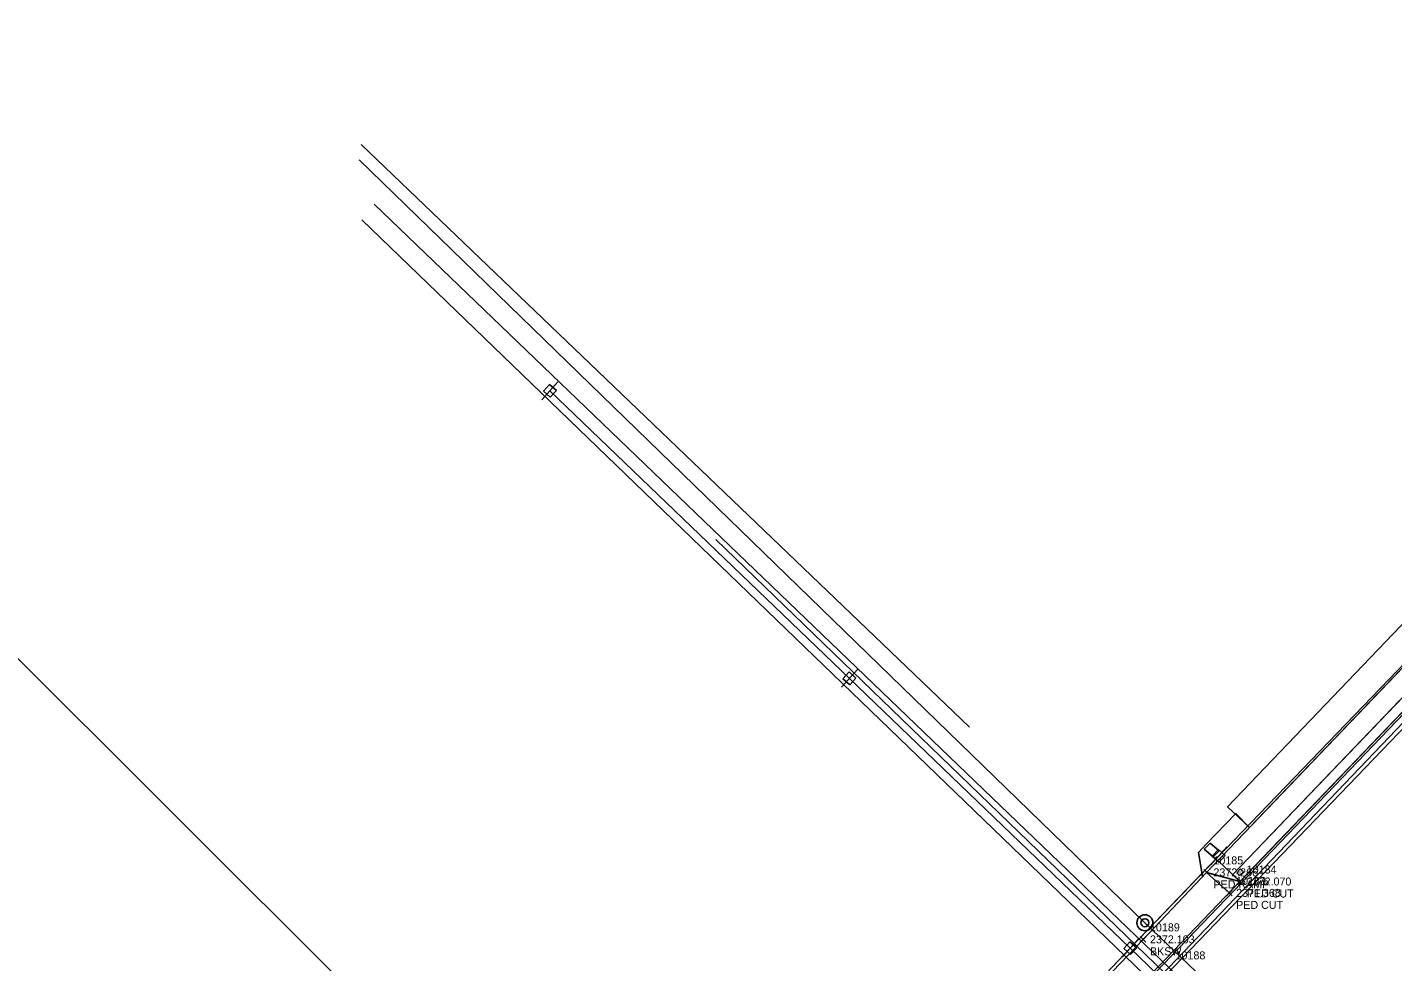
# Model space of a CAD drawing. Extents: x 2377639 to 2379738, y 729875 to 732734.
# Drawn here: x 2378181.6 to 2378522.8, y 730720.7 to 730954.4 of the extents above; entities that cross this region are included whole.
import ezdxf

# ---------------------------------------------------------------- set-up
doc = ezdxf.new("R2010")
doc.units = 0
for name, color, linetype in [('Default', 7, 'Continuous'), ('TOPO_CURBGTR_Back-of-Curb', 7, 'Continuous'), ('TOPO_CURBGTR_Face-of-Curb', 7, 'Continuous'), ('TOPO_CURBGTR_Lip-of-Gutter', 7, 'Continuous'), ('TOPO_DATA_Elevations', 7, 'Continuous'), ('TOPO_ELEC_Cable_Overhead-Exist', 7, 'Continuous'), ('TOPO_ELEC_Power-Pole', 7, 'Continuous'), ('TOPO_GAS_Line', 7, 'Continuous'), ('TOPO_LNDSCP_Misc', 7, 'Continuous'), ('TOPO_MISC_Flat-Asphalt', 7, 'Continuous'), ('TOPO_SAN_Plastic-Pipe', 7, 'Continuous'), ('TOPO_SAN_Sewer-Manhole', 7, 'Continuous'), ('TOPO_SW_Back', 7, 'Continuous'), ('TOPO_TELE_Overhead-Line', 7, 'Continuous'), ('TOPO_TRFSIGNL_Traf-Sig-Misc', 7, 'Continuous'), ('TOPO_TV_Cable-Overhead', 7, 'Continuous'), ('TOPO_WTRUTIL_Line', 7, 'Continuous')]:
    doc.layers.add(name, color=color, linetype=linetype)

# ---------------------------------------------------------------- blocks, each defined once
blk = doc.blocks.new('UP_1')
at = {"layer": 'Default'}
for p, q in [((-0.0145, 0.0145), (0.0145, 0.0145)), ((-0.0145, -0.0145), (-0.0145, 0.0145)), ((0, 0.0381), (0, -0.0381)), ((0.0145, 0.0145), (0.0145, -0.0145)), ((0.0145, -0.0145), (-0.0145, -0.0145))]:
    blk.add_line(p, q, dxfattribs=at)
blk = doc.blocks.new('JCTBOX_5')
at = {"layer": 'Default'}
for p, q in [((-0.0086, 0.0064), (0.0086, 0.0064)), ((-0.0086, 0.0064), (-0.0086, -0.0064)), ((0.0086, 0.0064), (0.0086, -0.0064)), ((-0.0086, -0.0064), (0.0086, -0.0064))]:
    blk.add_line(p, q, dxfattribs=at)
blk.add_text('SIG', height=0.00635, dxfattribs=at).set_placement((-0.0063, -0.0031))
blk = doc.blocks.new('MH_16')
at = {"layer": 'Default'}
for radius in [0.0254, 0.0127]:
    blk.add_circle((0, 0), radius, dxfattribs=at)

msp = doc.modelspace()

# ---------------------------------------------------------------- linework, layer by layer
at = {"layer": 'TOPO_CURBGTR_Back-of-Curb'}
msp.add_lwpolyline([(2378796.95, 731066.54), (2378792.22, 731061.65), (2378780.11, 731049.06), (2378765.8, 731034.16), (2378729.83, 730996.57), (2378708.78, 730974.71), (2378675.54, 730940.1), (2378596.07, 730857.01), (2378571.8, 730831.72), (2378484.65, 730740.78), (2378451.54, 730706.2), (2378383.47, 730635.07)], dxfattribs=at)
at = {"layer": 'TOPO_CURBGTR_Face-of-Curb'}
msp.add_lwpolyline([(2378797.32, 731066.2), (2378792.58, 731061.31), (2378780.47, 731048.72), (2378766.16, 731033.81), (2378730.19, 730996.23), (2378709.14, 730974.36), (2378675.9, 730939.76), (2378596.44, 730856.66), (2378572.16, 730831.38), (2378485.01, 730740.44), (2378451.9, 730705.86), (2378383.83, 730634.72)], dxfattribs=at)
at = {"layer": 'TOPO_CURBGTR_Lip-of-Gutter'}
msp.add_lwpolyline([(2378797.98, 731065.07), (2378794.67, 731061.59), (2378781.68, 731047.95), (2378751.07, 731015.98), (2378690.75, 730953), (2378584.09, 730841.86), (2378466.86, 730719.3), (2378390.08, 730639.26), (2378384.85, 730633.62), (2378384.85, 730633.62)], dxfattribs=at)
at = {"layer": 'TOPO_DATA_Elevations'}
for p, q in [((2378475.6, 730742.35), (2378477.02, 730743.77)), ((2378475.6, 730743.77), (2378477.02, 730742.35)), ((2378483.94, 730740.07), (2378485.35, 730741.49)), ((2378483.94, 730741.49), (2378485.35, 730740.07)), ((2378481.28, 730737.22), (2378482.7, 730738.63)), ((2378481.28, 730738.63), (2378482.7, 730737.22)), ((2378459.75, 730725.6), (2378461.17, 730727.01)), ((2378459.75, 730727.01), (2378461.17, 730725.6))]:
    msp.add_line(p, q, dxfattribs=at)
at = {"layer": 'TOPO_ELEC_Cable_Overhead-Exist'}
for p, q in [((2378387.03, 730791.57), (2378312.18, 730863.48)), ((2378457.25, 730724.11), (2378535.31, 730805.28)), ((2378457.25, 730724.11), (2378387.03, 730791.57)), ((2378457.25, 730724.11), (2378479.34, 730747.2)), ((2378314.05, 730574.41), (2378457.25, 730724.11)), ((2378553.19, 730631.94), (2378457.25, 730724.11))]:
    msp.add_line(p, q, dxfattribs=at)
at = {"layer": 'TOPO_GAS_Line'}
msp.add_line((2378417.04, 730779.39), (2378265.05, 730925.04), dxfattribs=at)
at = {"layer": 'TOPO_LNDSCP_Misc'}
msp.add_lwpolyline([(2378487.03, 730754.25), (2378556.6, 730826.93), (2378551.15, 730832.15), (2378481.58, 730759.47)], close=True, dxfattribs=at)
at = {"layer": 'TOPO_MISC_Flat-Asphalt'}
msp.add_lwpolyline([(2378482.84, 730742.51), (2378569.94, 730833.5), (2378571.8, 730831.72), (2378484.69, 730740.74)], close=True, dxfattribs=at)
at = {"layer": 'TOPO_SAN_Plastic-Pipe'}
for p, q in [((2378460.89, 730730.47), (2378264.52, 730921.2)), ((2378737.85, 730466.14), (2378460.89, 730730.47))]:
    msp.add_line(p, q, dxfattribs=at)
at = {"layer": 'TOPO_SW_Back'}
for p, q in [((2378474.28, 730748.01), (2378475.3, 730741.99)), ((2378476.31, 730743.06), (2378481.95, 730737.97)), ((2378484.65, 730740.78), (2378479.16, 730746.03))]:
    msp.add_line(p, q, dxfattribs=at)
for points in [[(2378476.31, 730743.06), (2378553.89, 730824.05), (2378569.96, 730840.68)], [(2378570, 730833.46), (2378569.99, 730833.46), (2378482.84, 730742.51), (2378482.84, 730742.51)], [(2378474.28, 730748.01), (2378476.23, 730750.1), (2378483.64, 730757.81), (2378487.03, 730754.25)], [(2378449.02, 730714.37), (2378460.46, 730726.31), (2378476.31, 730743.06), (2378484.65, 730740.78)]]:
    msp.add_lwpolyline(points, dxfattribs=at)
msp.add_lwpolyline([(2378477.22, 730750.38), (2378479.49, 730748.42), (2378477.99, 730746.93), (2378475.73, 730748.89)], close=True, dxfattribs=at)
at = {"layer": 'TOPO_TELE_Overhead-Line'}
for p, q in [((2378751.05, 730446.34), (2378268.25, 730910.16)), ((2378564.13, 730622.97), (2378353.69, 730826.29))]:
    msp.add_line(p, q, dxfattribs=at)
at = {"layer": 'TOPO_TV_Cable-Overhead'}
msp.add_line((2378746.7, 730441.54), (2378265.21, 730906.27), dxfattribs=at)
at = {"layer": 'TOPO_WTRUTIL_Line'}
for p, q in [((2378391.81, 730640.09), (2378830.45, 731096.49)), ((2378156.61, 730819.02), (2378357.13, 730619.05))]:
    msp.add_line(p, q, dxfattribs=at)

# ---------------------------------------------------------------- block references
at = {"layer": 'TOPO_ELEC_Power-Pole', "xscale": 78.74, "yscale": 78.74000000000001, "rotation": -41.90525780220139}
for p in [(2378312.18, 730863.48), (2378387.03, 730791.57), (2378479.34, 730747.2), (2378457.25, 730724.11)]:
    msp.add_blockref('UP_1', p, dxfattribs=at)
at = {"layer": 'TOPO_SAN_Sewer-Manhole', "xscale": 78.74000000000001, "yscale": 78.74000000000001}
msp.add_blockref('MH_16', (2378460.89, 730730.47), dxfattribs=at)
at = {"layer": 'TOPO_TRFSIGNL_Traf-Sig-Misc', "xscale": 78.74, "yscale": 78.74, "rotation": 45.782319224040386}
msp.add_blockref('JCTBOX_5', (2378484.67, 730743.1), dxfattribs=at)

# ---------------------------------------------------------------- texts
at = {"layer": 'TOPO_DATA_Elevations'}
for s, p in [('10185', (2378478.02, 730745.06)), ('2372.266', (2378478.02, 730742.06)), ('10184', (2378486.35, 730742.78)), ('PED RAMP', (2378478.02, 730739.06)), ('10183', (2378483.7, 730739.93)), ('2372.070', (2378486.35, 730739.78)), ('2371.368', (2378483.7, 730736.93)), ('PED CUT', (2378483.7, 730733.93)), ('PED CUT', (2378486.35, 730736.78)), ('10189', (2378462.17, 730728.31)), ('2372.103', (2378462.17, 730725.31)), ('BKSW', (2378462.17, 730722.31)), ('10188', (2378468.57, 730721.3))]:
    msp.add_text(s, height=2, dxfattribs=at).set_placement(p)

doc.saveas('drawing.dxf')
